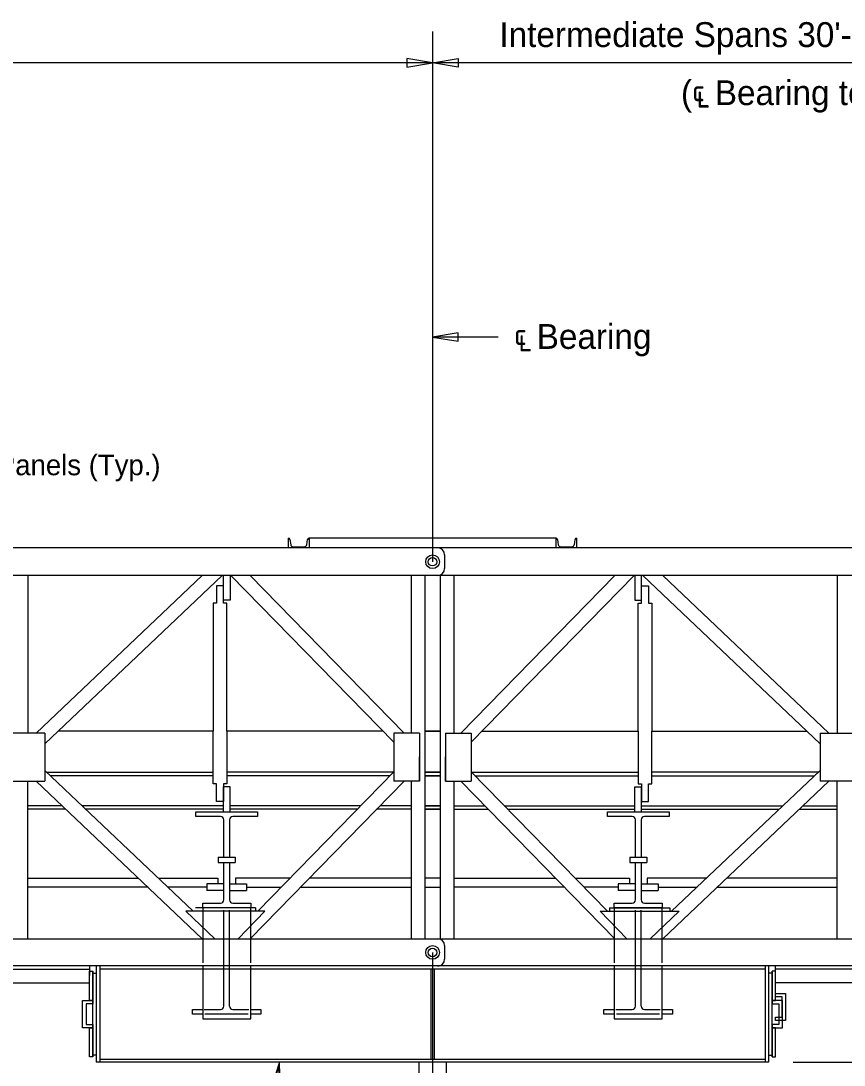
# Model space of a CAD drawing. Extents: x 3 to 58.1, y 3.3 to 34.2.
# Drawn here: x 37.33 to 47.33, y 21.56 to 34.25 of the extents above; entities that cross this region are included whole.
import ezdxf

# ---------------------------------------------------------------- set-up
doc = ezdxf.new("R2010")
doc.units = 0
for name, color, linetype in [('CL_Minor', 7, 'Continuous'), ('Dimension', 7, 'Continuous'), ('SteelMisc', 7, 'Continuous'), ('SteelMisc_h', 7, 'Continuous'), ('TextStructures', 7, 'Continuous')]:
    doc.layers.add(name, color=color, linetype=linetype)

msp = doc.modelspace()

# ---------------------------------------------------------------- linework, layer by layer
at = {"layer": 'CL_Minor'}
for p, q in [((42.335, 34.121), (42.335, 27.675)), ((42.335, 22.925), (42.335, 7.572))]:
    msp.add_line(p, q, dxfattribs=at)
at = {"layer": 'Dimension'}
for p, q in [((43.132, 30.406), (42.335, 30.406)), ((46.715, 21.592), (52.811, 21.592))]:
    msp.add_line(p, q, dxfattribs=at)
for points in [[(42.335, 33.74), (42.022, 33.792), (42.022, 33.687)], [(42.335, 33.74), (42.647, 33.792), (42.647, 33.687)], [(42.335, 30.406), (42.647, 30.354), (42.647, 30.459)], [(40.478, 21.592), (40.378, 21.292), (40.483, 21.275)]]:
    msp.add_lwpolyline(points, close=True, dxfattribs=at)
msp.add_open_spline([(39.329, 18.506), (39.72, 18.506), (39.897, 18.616), (40.384, 20.985), (40.478, 21.592)], degree=2, dxfattribs=at)
at = {"layer": 'SteelMisc'}
for p, q in [((40.585, 27.842), (40.585, 27.96)), ((40.602, 27.945), (40.612, 27.882)), ((40.808, 27.882), (40.818, 27.945)), ((43.835, 27.96), (40.835, 27.96)), ((40.835, 27.96), (40.835, 27.842)), ((43.835, 27.842), (43.835, 27.96)), ((43.852, 27.945), (43.862, 27.882)), ((44.058, 27.882), (44.068, 27.945)), ((44.085, 27.96), (44.085, 27.842)), ((50.696, 27.842), (28.969, 27.842)), ((40.835, 27.842), (40.585, 27.842)), ((40.642, 27.856), (40.777, 27.856)), ((44.085, 27.842), (43.835, 27.842)), ((43.892, 27.856), (44.027, 27.856)), ((42.482, 27.759), (42.482, 27.592)), ((50.696, 27.509), (28.969, 27.509)), ((37.418, 27.509), (37.418, 25.592)), ((39.538, 27.509), (37.521, 25.592)), ((39.78, 27.509), (37.626, 25.463)), ((39.794, 27.208), (39.794, 27.509)), ((39.875, 27.509), (39.875, 27.208)), ((41.866, 25.48), (39.885, 27.509)), ((41.989, 25.592), (40.118, 27.509)), ((42.074, 27.509), (42.074, 25.592)), ((42.241, 27.509), (42.241, 23.092)), ((42.428, 27.509), (42.428, 23.092)), ((42.595, 27.509), (42.595, 25.592)), ((42.68, 25.592), (44.551, 27.509)), ((42.803, 25.48), (44.784, 27.509)), ((44.794, 27.509), (44.794, 27.208)), ((44.875, 27.208), (44.875, 27.509)), ((44.889, 27.509), (47.043, 25.463)), ((45.131, 27.509), (47.149, 25.592)), ((47.251, 27.509), (47.251, 25.592)), ((39.875, 27.208), (39.794, 27.208)), ((44.794, 27.208), (44.875, 27.208)), ((37.626, 25.592), (37.043, 25.592)), ((37.626, 25.592), (37.626, 25.009)), ((39.669, 25.616), (37.787, 25.616)), ((41.734, 25.616), (39.836, 25.616)), ((42.178, 25.592), (41.866, 25.592)), ((41.866, 25.592), (41.866, 25.009)), ((42.178, 25.592), (42.178, 25.009)), ((42.428, 25.616), (42.241, 25.616)), ((42.241, 25.616), (42.428, 25.616)), ((42.491, 25.592), (42.491, 25.009)), ((42.491, 25.592), (42.803, 25.592)), ((42.803, 25.592), (42.803, 25.009)), ((42.936, 25.616), (44.833, 25.616)), ((45, 25.616), (46.882, 25.616)), ((47.043, 25.592), (47.043, 25.009)), ((47.043, 25.592), (47.626, 25.592)), ((42.178, 25.009), (42.178, 25.303)), ((42.491, 25.009), (42.491, 25.303)), ((37.626, 25.138), (39.429, 23.425)), ((47.043, 25.138), (45.24, 23.425)), ((37.043, 25.009), (37.626, 25.009)), ((37.418, 23.092), (37.418, 25.009)), ((37.521, 25.009), (39.538, 23.092)), ((37.65, 25.116), (39.669, 25.116)), ((39.669, 25.074), (37.694, 25.074)), ((41.861, 25.116), (39.836, 25.116)), ((41.82, 25.074), (39.836, 25.074)), ((40.118, 23.092), (41.989, 25.009)), ((40.211, 23.425), (41.866, 25.121)), ((42.178, 25.009), (41.866, 25.009)), ((42.074, 25.009), (42.074, 23.092)), ((42.241, 25.116), (42.428, 25.116)), ((42.428, 25.116), (42.241, 25.116)), ((42.241, 25.074), (42.428, 25.074)), ((42.428, 25.074), (42.241, 25.074)), ((42.491, 25.009), (42.803, 25.009)), ((42.595, 25.009), (42.595, 23.092)), ((44.551, 23.092), (42.68, 25.009)), ((44.459, 23.425), (42.803, 25.121)), ((42.809, 25.116), (44.833, 25.116)), ((42.85, 25.074), (44.833, 25.074)), ((47.019, 25.116), (45, 25.116)), ((45, 25.074), (46.975, 25.074)), ((47.149, 25.009), (45.131, 23.092)), ((47.626, 25.009), (47.043, 25.009)), ((47.251, 23.092), (47.251, 25.009)), ((39.875, 24.937), (39.794, 24.937)), ((39.794, 24.634), (39.794, 24.937)), ((39.875, 24.634), (39.875, 24.937)), ((44.794, 24.634), (44.794, 24.937)), ((44.794, 24.937), (44.875, 24.937)), ((44.875, 24.634), (44.875, 24.937)), ((37.836, 24.709), (37.418, 24.709)), ((37.88, 24.667), (37.418, 24.667)), ((39.794, 24.709), (38.078, 24.709)), ((39.794, 24.667), (38.122, 24.667)), ((39.46, 24.578), (39.46, 24.634)), ((39.46, 24.634), (40.21, 24.634)), ((41.464, 24.709), (39.875, 24.709)), ((41.423, 24.667), (39.875, 24.667)), ((40.21, 24.634), (40.21, 24.578)), ((42.074, 24.667), (41.656, 24.667)), ((42.074, 24.709), (41.697, 24.709)), ((42.428, 24.709), (42.241, 24.709)), ((42.241, 24.709), (42.428, 24.709)), ((42.241, 24.667), (42.428, 24.667)), ((42.428, 24.667), (42.241, 24.667)), ((42.595, 24.709), (42.973, 24.709)), ((42.595, 24.667), (43.013, 24.667)), ((43.206, 24.709), (44.794, 24.709)), ((43.246, 24.667), (44.794, 24.667)), ((44.46, 24.578), (44.46, 24.634)), ((44.46, 24.634), (45.21, 24.634)), ((44.875, 24.709), (46.591, 24.709)), ((44.875, 24.667), (46.547, 24.667)), ((45.21, 24.634), (45.21, 24.578)), ((46.789, 24.667), (47.251, 24.667)), ((46.833, 24.709), (47.251, 24.709)), ((39.759, 24.578), (39.46, 24.578)), ((39.801, 24.082), (39.801, 24.536)), ((39.869, 24.536), (39.869, 24.082)), ((40.21, 24.578), (39.911, 24.578)), ((44.759, 24.578), (44.46, 24.578)), ((44.8, 24.082), (44.8, 24.536)), ((44.869, 24.536), (44.869, 24.082)), ((45.21, 24.578), (44.91, 24.578)), ((39.731, 24.082), (39.731, 24.019)), ((39.731, 24.082), (39.939, 24.082)), ((39.731, 24.019), (39.939, 24.019)), ((39.801, 23.565), (39.801, 24.019)), ((39.869, 24.019), (39.869, 23.565)), ((39.939, 24.082), (39.939, 24.019)), ((44.73, 24.082), (44.73, 24.019)), ((44.73, 24.082), (44.939, 24.082)), ((44.73, 24.019), (44.939, 24.019)), ((44.8, 23.565), (44.8, 24.019)), ((44.869, 24.019), (44.869, 23.565)), ((44.939, 24.082), (44.939, 24.019)), ((39.592, 23.759), (39.592, 23.678)), ((39.801, 23.759), (39.592, 23.759)), ((39.728, 23.828), (39.728, 23.759)), ((39.869, 23.759), (40.077, 23.759)), ((39.941, 23.828), (39.941, 23.759)), ((40.077, 23.759), (40.077, 23.678)), ((44.592, 23.759), (44.592, 23.678)), ((44.8, 23.759), (44.592, 23.759)), ((44.728, 23.828), (44.728, 23.759)), ((44.869, 23.759), (45.077, 23.759)), ((44.941, 23.828), (44.941, 23.759)), ((45.077, 23.759), (45.077, 23.678)), ((39.801, 23.678), (39.592, 23.678)), ((39.869, 23.678), (40.077, 23.678)), ((44.8, 23.678), (44.592, 23.678)), ((44.869, 23.678), (45.077, 23.678)), ((39.543, 23.467), (39.543, 23.523)), ((39.543, 23.523), (39.759, 23.523)), ((39.911, 23.523), (40.126, 23.523)), ((40.126, 23.523), (40.126, 23.467)), ((44.543, 23.467), (44.543, 23.523)), ((44.543, 23.523), (44.759, 23.523)), ((44.91, 23.523), (45.126, 23.523)), ((45.126, 23.523), (45.126, 23.467)), ((40.298, 23.425), (39.339, 23.425)), ((39.339, 23.425), (39.689, 23.092)), ((40.186, 23.467), (39.454, 23.467)), ((39.543, 23.467), (39.543, 22.798)), ((39.801, 22.273), (39.801, 23.438)), ((39.869, 22.273), (39.869, 23.438)), ((39.973, 23.092), (40.298, 23.425)), ((40.126, 22.798), (40.126, 23.467)), ((40.186, 23.467), (40.186, 23.427)), ((44.371, 23.425), (45.331, 23.425)), ((44.697, 23.092), (44.371, 23.425)), ((44.483, 23.467), (45.216, 23.467)), ((44.483, 23.467), (44.483, 23.427)), ((44.543, 23.467), (44.543, 22.798)), ((44.8, 22.273), (44.8, 23.438)), ((44.869, 22.273), (44.869, 23.438)), ((45.331, 23.425), (44.98, 23.092)), ((45.126, 22.798), (45.126, 23.467)), ((45.216, 23.467), (45.216, 23.424)), ((28.969, 23.092), (50.696, 23.092)), ((42.482, 23.009), (42.482, 22.842)), ((50.696, 22.761), (28.969, 22.761)), ((38.168, 22.759), (38.168, 22.644)), ((38.251, 22.759), (38.251, 21.592)), ((38.251, 22.759), (38.251, 21.592)), ((38.293, 22.759), (38.293, 21.592)), ((38.293, 22.727), (46.376, 22.727)), ((39.543, 22.761), (39.543, 22.12)), ((40.126, 22.12), (40.126, 22.761)), ((42.314, 22.727), (42.314, 21.624)), ((42.355, 22.727), (42.355, 21.624)), ((44.543, 22.761), (44.543, 22.12)), ((45.126, 22.12), (45.126, 22.761)), ((46.376, 22.759), (46.376, 21.592)), ((46.418, 22.759), (46.418, 21.592)), ((46.891, 22.761), (46.501, 22.761)), ((46.501, 22.696), (46.501, 22.761)), ((38.168, 22.342), (38.168, 22.696)), ((38.168, 22.696), (38.21, 22.696)), ((38.21, 21.655), (38.21, 22.696)), ((38.21, 22.696), (38.21, 22.342)), ((38.21, 22.675), (38.251, 22.675)), ((38.251, 22.675), (38.251, 21.675)), ((46.418, 22.675), (46.418, 21.675)), ((46.46, 22.675), (46.418, 22.675)), ((46.46, 21.655), (46.46, 22.696)), ((46.46, 22.696), (46.46, 22.342)), ((46.501, 22.696), (46.46, 22.696)), ((46.501, 22.342), (46.501, 22.696)), ((33.724, 22.554), (38.168, 22.554)), ((50.696, 22.554), (46.501, 22.554)), ((38.085, 22.342), (38.21, 22.342)), ((38.085, 22.009), (38.085, 22.342)), ((38.21, 22.342), (38.168, 22.342)), ((38.21, 22.342), (38.21, 22.3)), ((46.46, 22.342), (46.501, 22.342)), ((46.585, 22.342), (46.46, 22.342)), ((46.46, 22.342), (46.46, 22.3)), ((46.585, 22.009), (46.585, 22.342)), ((38.21, 22.3), (38.126, 22.3)), ((38.126, 22.3), (38.126, 22.05)), ((39.418, 22.176), (39.418, 22.231)), ((39.418, 22.231), (39.543, 22.231)), ((39.562, 22.231), (39.759, 22.231)), ((39.911, 22.231), (40.102, 22.231)), ((40.126, 22.231), (40.251, 22.231)), ((40.251, 22.231), (40.251, 22.176)), ((44.418, 22.176), (44.418, 22.231)), ((44.418, 22.231), (44.543, 22.231)), ((44.562, 22.231), (44.759, 22.231)), ((44.91, 22.231), (45.102, 22.231)), ((45.126, 22.231), (45.251, 22.231)), ((45.251, 22.231), (45.251, 22.176)), ((46.46, 22.3), (46.543, 22.3)), ((46.543, 22.3), (46.543, 22.05)), ((39.543, 22.12), (40.126, 22.12)), ((44.543, 22.12), (45.126, 22.12)), ((38.21, 22.009), (38.085, 22.009)), ((38.126, 22.05), (38.21, 22.05)), ((38.168, 21.655), (38.168, 22.009)), ((38.168, 22.009), (38.21, 22.009)), ((38.21, 22.05), (38.21, 22.009)), ((38.21, 22.009), (38.21, 21.655)), ((46.543, 22.05), (46.46, 22.05)), ((46.46, 22.05), (46.46, 22.009)), ((46.46, 22.009), (46.585, 22.009)), ((46.501, 22.009), (46.46, 22.009)), ((46.46, 22.009), (46.46, 21.655)), ((46.501, 21.655), (46.501, 22.009)), ((38.21, 21.655), (38.168, 21.655)), ((38.251, 21.675), (38.21, 21.675)), ((46.418, 21.592), (38.251, 21.592)), ((46.376, 21.624), (38.293, 21.624)), ((42.168, 21.592), (42.168, 21.455)), ((42.501, 21.592), (42.501, 21.454)), ((46.418, 21.675), (46.46, 21.675)), ((46.46, 21.655), (46.501, 21.655))]:
    msp.add_line(p, q, dxfattribs=at)
for points in [[(39.836, 25.616), (39.836, 27.17), (39.794, 27.17), (39.794, 27.383), (39.711, 27.383), (39.711, 27.17), (39.669, 27.17), (39.669, 25.616)], [(44.833, 25.616), (44.833, 27.17), (44.875, 27.17), (44.875, 27.383), (44.958, 27.383), (44.958, 27.17), (45, 27.17), (45, 25.616)], [(39.836, 25.616), (39.836, 24.975), (39.794, 24.975), (39.794, 24.762), (39.711, 24.762), (39.711, 24.975), (39.669, 24.975), (39.669, 25.616)], [(44.833, 25.616), (44.833, 24.975), (44.875, 24.975), (44.875, 24.762), (44.958, 24.762), (44.958, 24.975), (45, 24.975), (45, 25.616)], [(37.418, 23.828), (38.766, 23.828)], [(39.009, 23.828), (39.728, 23.828)], [(40.604, 23.828), (39.941, 23.828)], [(42.074, 23.828), (40.836, 23.828)], [(42.428, 23.828), (42.241, 23.828)], [(42.595, 23.828), (43.833, 23.828)], [(44.066, 23.828), (44.728, 23.828)], [(45.664, 23.828), (44.941, 23.828)], [(47.251, 23.828), (45.906, 23.828)], [(38.879, 23.718), (37.418, 23.718)], [(39.592, 23.718), (39.121, 23.718)], [(40.077, 23.718), (40.497, 23.718)], [(40.73, 23.718), (42.074, 23.718)], [(42.241, 23.718), (42.428, 23.718)], [(43.94, 23.718), (42.595, 23.718)], [(44.592, 23.718), (44.173, 23.718)], [(45.077, 23.718), (45.548, 23.718)], [(45.79, 23.718), (47.251, 23.718)], [(40.126, 23.467), (39.835, 23.467), (39.543, 23.467)], [(45.126, 23.467), (44.835, 23.467), (44.543, 23.467)], [(39.543, 22.176), (39.418, 22.176)], [(40.094, 22.176), (39.57, 22.176)], [(40.251, 22.176), (40.126, 22.176)], [(44.543, 22.176), (44.418, 22.176)], [(45.094, 22.176), (44.57, 22.176)], [(45.251, 22.176), (45.126, 22.176)]]:
    msp.add_lwpolyline(points, dxfattribs=at)
msp.add_lwpolyline([(46.501, 22.425), (46.624, 22.425), (46.624, 22.098), (46.501, 22.098), (46.501, 22.139), (46.583, 22.139), (46.583, 22.384), (46.501, 22.384)], close=True, dxfattribs=at)
for centre, radius in [((42.335, 27.675), 0.0833), ((42.335, 27.675), 0.0521), ((42.335, 22.925), 0.0833), ((42.335, 22.925), 0.0521)]:
    msp.add_circle(centre, radius, dxfattribs=at)
for centre, radius, start, end in [((40.585, 27.942), 0.0173, 9.5, 90), ((40.835, 27.942), 0.0173, 90, 170.5), ((43.835, 27.942), 0.0173, 9.5, 90), ((44.085, 27.942), 0.0173, 90, 170.5), ((40.642, 27.887), 0.0306, 189.5, 270), ((40.777, 27.887), 0.0306, 270, 350.5), ((42.399, 27.759), 0.0833, 0, 90), ((43.892, 27.887), 0.0306, 189.5, 270), ((44.027, 27.887), 0.0306, 270, 350.5), ((42.399, 27.592), 0.0833, 270, 0), ((39.759, 24.536), 0.0417, 0, 90), ((39.911, 24.536), 0.0417, 90, 180), ((44.759, 24.536), 0.0417, 0, 90), ((44.91, 24.536), 0.0417, 90, 180), ((39.759, 23.565), 0.0417, 270, 360), ((39.911, 23.565), 0.0417, 180, 270), ((44.759, 23.565), 0.0417, 270, 360), ((44.91, 23.565), 0.0417, 180, 270), ((42.399, 23.009), 0.0833, 0, 90), ((42.399, 22.842), 0.0833, 270, 0), ((39.759, 22.273), 0.0417, 270, 0), ((39.911, 22.273), 0.0417, 180, 270), ((44.759, 22.273), 0.0417, 270, 0), ((44.91, 22.273), 0.0417, 180, 270)]:
    msp.add_arc(centre, radius, start, end, dxfattribs=at)
at = {"layer": 'SteelMisc_h'}
for p, q in [((33.724, 22.721), (38.168, 22.721)), ((50.696, 22.721), (46.501, 22.721))]:
    msp.add_line(p, q, dxfattribs=at)
at = {"layer": 'TextStructures'}
for points in [[(42.256, 33.74), (28.432, 33.74), (28.432, 33.585), (28.297, 33.895), (28.297, 33.74), (14.831, 33.74)], [(54.378, 33.74), (49.563, 33.74), (49.563, 33.585), (49.428, 33.895), (49.428, 33.74), (42.256, 33.74)]]:
    msp.add_lwpolyline(points, dxfattribs=at)

# ---------------------------------------------------------------- texts
at = {"layer": 'Dimension'}
msp.add_text('℄ Bearing', height=0.3024, dxfattribs=at).set_placement((43.324, 30.262))
at = {"layer": 'TextStructures'}
for s, height, p in [('Intermediate Spans 30\'-0" Min. ; 60\'-0" Max.', 0.3024, (43.147, 33.931)), ('(℄ Bearing to ℄ Bearing)', 0.3024, (45.353, 33.225)), ('AB1 Truss Panels (Typ.)', 0.25, (35.39, 28.726))]:
    msp.add_text(s, height=height, dxfattribs=at).set_placement(p)

doc.saveas('drawing.dxf')
